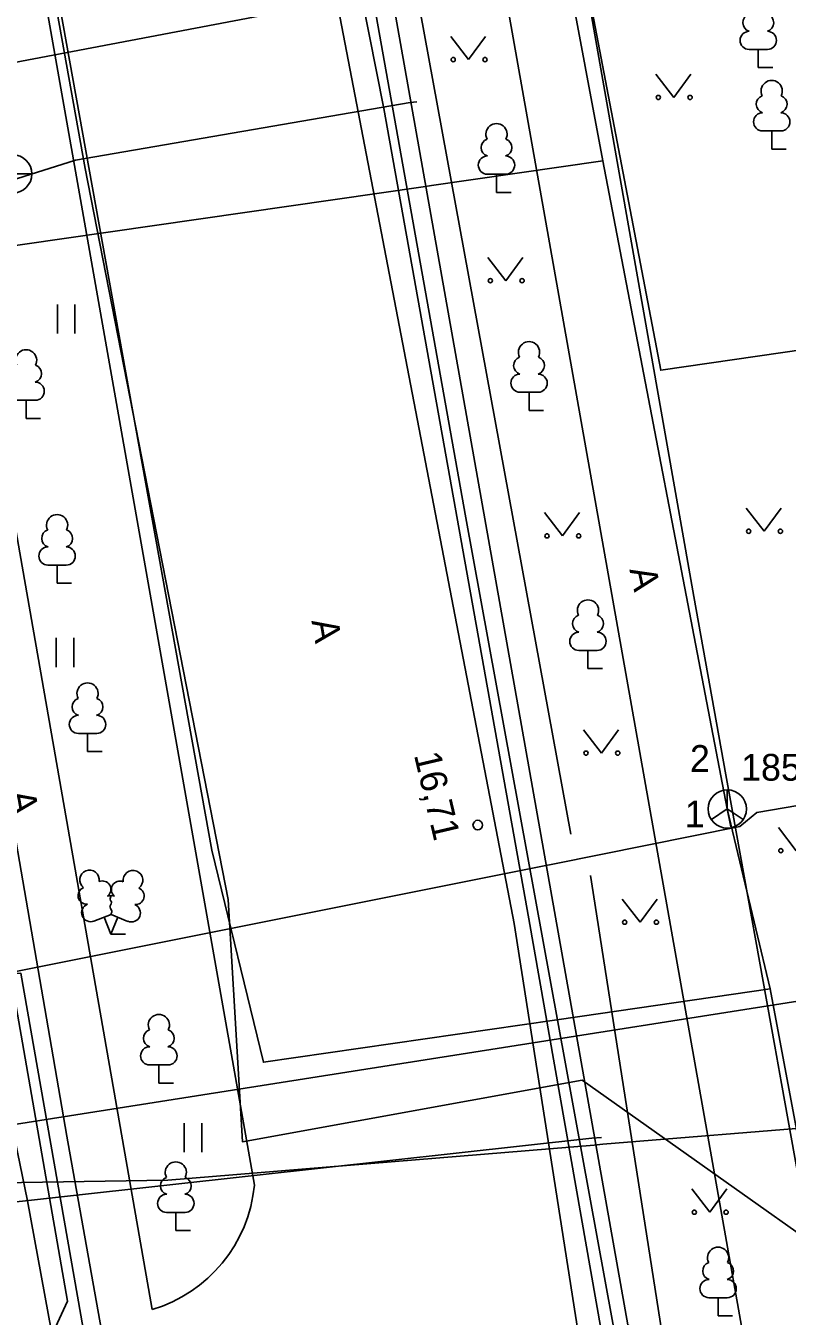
# Model space of a CAD drawing. Extents: x 713540 to 713867, y 6589774 to 6590061.
# Drawn here: x 713700.77 to 713720.66, y 6589807.61 to 6589841.34 of the extents above; entities that cross this region are included whole.
import ezdxf

# ---------------------------------------------------------------- set-up
doc = ezdxf.new("R2010")
doc.units = 0
for name, color, linetype in [('HALJASTUS', 7, 'Continuous'), ('HOONE', 7, 'Continuous'), ('KAEVU_NR', 7, 'Continuous'), ('KKAEV', 7, 'Continuous'), ('KORGUS', 7, 'Continuous'), ('KPKAABEL', 7, 'Continuous'), ('KTRASS', 7, 'Continuous'), ('MPKAABEL', 7, 'Continuous'), ('PUU', 7, 'Continuous'), ('SIKAEV', 7, 'Continuous'), ('SITRASS', 7, 'Continuous'), ('TEE', 7, 'Continuous'), ('TORU NR', 7, 'Continuous'), ('TTRASS', 7, 'Continuous'), ('VTRASS', 7, 'Continuous'), ('Слой 1', 7, 'Continuous')]:
    doc.layers.add(name, color=color, linetype=linetype)

msp = doc.modelspace()

# ---------------------------------------------------------------- linework, layer by layer
at = {"layer": 'HALJASTUS'}
for p, q in [((713711.877, 6589841.067), (713712.34, 6589840.46)), ((713712.34, 6589840.46), (713712.786, 6589841.067)), ((713717.237, 6589840.077), (713717.7, 6589839.47)), ((713717.7, 6589839.47), (713718.146, 6589840.077)), ((713712.847, 6589835.287), (713713.31, 6589834.68)), ((713713.31, 6589834.68), (713713.756, 6589835.287)), ((713701.6, 6589834.059), (713701.6, 6589833.298)), ((713702.055, 6589834.059), (713702.055, 6589833.298)), ((713714.327, 6589828.617), (713714.79, 6589828.01)), ((713714.79, 6589828.01), (713715.236, 6589828.617)), ((713719.597, 6589828.737), (713720.06, 6589828.13)), ((713720.06, 6589828.13), (713720.506, 6589828.737)), ((713701.567, 6589825.341), (713701.567, 6589824.58)), ((713702.023, 6589825.341), (713702.023, 6589824.58)), ((713715.347, 6589822.937), (713715.81, 6589822.33)), ((713715.81, 6589822.33), (713716.256, 6589822.937)), ((713720.437, 6589820.387), (713720.9, 6589819.78)), ((713716.357, 6589818.517), (713716.82, 6589817.91)), ((713716.82, 6589817.91), (713717.266, 6589818.517)), ((713704.912, 6589812.657), (713704.912, 6589811.896)), ((713705.367, 6589812.657), (713705.367, 6589811.896)), ((713718.177, 6589810.937), (713718.64, 6589810.33)), ((713718.64, 6589810.33), (713719.086, 6589810.937))]:
    msp.add_line(p, q, dxfattribs=at)
for points in [[(713705.159, 6589874.056), (713715.01, 6589820.21)], [(713718.296, 6589801.399), (713715.53, 6589819.13)]]:
    msp.add_lwpolyline(points, dxfattribs=at)
for centre in [(713711.939, 6589840.46), (713712.768, 6589840.46), (713717.299, 6589839.47), (713718.128, 6589839.47), (713712.909, 6589834.68), (713713.738, 6589834.68), (713719.659, 6589828.13), (713720.488, 6589828.13), (713714.389, 6589828.01), (713715.218, 6589828.01), (713715.409, 6589822.33), (713716.238, 6589822.33), (713720.499, 6589819.78), (713716.419, 6589817.91), (713717.248, 6589817.91), (713718.239, 6589810.33), (713719.068, 6589810.33)]:
    msp.add_circle(centre, 0.055, dxfattribs=at)
at = {"layer": 'HOONE'}
for points in [[(713671.44, 6589834.87), (713687.15, 6589837.855), (713710.253, 6589842.245), (713710.463, 6589842.286), (713715.96, 6589843.33), (713717, 6589843.42)], [(713691.059, 6589811.144), (713725.368, 6589816.545)]]:
    msp.add_lwpolyline(points, dxfattribs=at)
at = {"layer": 'KKAEV'}
msp.add_line((713699.931, 6589837.471), (713700.931, 6589837.471), dxfattribs=at)
msp.add_circle((713700.431, 6589837.471), 0.5, dxfattribs=at)
at = {"layer": 'KORGUS'}
msp.add_circle((713712.58, 6589820.45), 0.125, dxfattribs=at)
at = {"layer": 'KPKAABEL'}
for points in [[(713700.447, 6589886.145), (713701.061, 6589885.962), (713701.248, 6589885.623), (713703.334, 6589872.63), (713704.833, 6589863.294), (713707.784, 6589847.812), (713713.528, 6589817.88), (713715.336, 6589806.351), (713717.846, 6589793.663), (713718.024, 6589793.474), (713722.293, 6589793.794), (713723.951, 6589793.699), (713735.68, 6589793.289), (713735.884, 6589793.19), (713735.895, 6589792.126)], [(713736.4, 6589792.129), (713736.273, 6589793.498), (713736.211, 6589793.555), (713728.781, 6589794.331), (713726.012, 6589794.505), (713722.026, 6589794.438), (713718.442, 6589794.01), (713718.345, 6589794.091), (713715.955, 6589806.397), (713713.917, 6589817.996), (713710.127, 6589839.185), (713708.399, 6589847.895)]]:
    msp.add_lwpolyline(points, dxfattribs=at)
at = {"layer": 'KTRASS'}
msp.add_lwpolyline([(713719.19, 6589820.4), (713719.1, 6589820.87)], dxfattribs=at)
at = {"layer": 'MPKAABEL'}
for points in [[(713694.011, 6589938.961), (713692.89, 6589933.64), (713698.13, 6589925.84), (713701.56, 6589922.83), (713707.37, 6589919), (713707.983, 6589913.318), (713708.27, 6589910.66), (713700.37, 6589905.55), (713699.23, 6589901.46), (713701.24, 6589889.8), (713704.212, 6589873.404), (713706.92, 6589858.46), (713712.25, 6589828.58), (713717.93, 6589797.45), (713721.28, 6589780.69), (713722.515, 6589774.068)], [(713733.391, 6589792.128), (713732.429, 6589795.958), (713729.329, 6589801.34), (713725.485, 6589806.569), (713715.308, 6589813.781), (713706.433, 6589812.173), (713706.056, 6589818.501), (713702.321, 6589837.617), (713696.514, 6589869.947), (713694.084, 6589874.558), (713687.448, 6589873.302), (713670.227, 6589869.773), (713666.658, 6589869.039)], [(713710.985, 6589839.36), (713710.816, 6589839.338), (713702.066, 6589837.833), (713696.99, 6589836.226), (713687.666, 6589835.577)], [(713633.563, 6589809.916), (713654.618, 6589810.191), (713654.93, 6589810.196), (713666.083, 6589810.341), (713690.526, 6589810.39), (713694.651, 6589811.012), (713704.48, 6589811.17), (713715.623, 6589812.086), (713715.845, 6589812.105), (713721.87, 6589812.6), (713723.29, 6589804.72), (713724.128, 6589800.265), (713724.224, 6589799.756), (713726.25, 6589788.99), (713732.01, 6589789.32)], [(713715.814, 6589812.279), (713715.56, 6589812.268), (713706.735, 6589811.288), (713694.54, 6589809.938), (713689.415, 6589809.721), (713680.928, 6589809.941), (713675.266, 6589809.808), (713670.351, 6589809.668), (713669.919, 6589807.051), (713670.914, 6589801.264), (713671.131, 6589797.032)]]:
    msp.add_lwpolyline(points, dxfattribs=at)
at = {"layer": 'PUU'}
for p, q in [((713720.15, 6589840.725), (713719.67, 6589840.725)), ((713719.91, 6589840.25), (713719.91, 6589840.725)), ((713720.29, 6589840.25), (713719.91, 6589840.25)), ((713720.5, 6589838.595), (713720.02, 6589838.595)), ((713720.26, 6589838.12), (713720.26, 6589838.595)), ((713720.64, 6589838.12), (713720.26, 6589838.12)), ((713713.31, 6589837.465), (713712.83, 6589837.465)), ((713713.07, 6589836.99), (713713.07, 6589837.465)), ((713713.45, 6589836.99), (713713.07, 6589836.99)), ((713701.02, 6589831.555), (713700.54, 6589831.555)), ((713700.78, 6589831.08), (713700.78, 6589831.555)), ((713714.16, 6589831.765), (713713.68, 6589831.765)), ((713713.92, 6589831.29), (713713.92, 6589831.765)), ((713714.3, 6589831.29), (713713.92, 6589831.29)), ((713701.16, 6589831.08), (713700.78, 6589831.08)), ((713701.83, 6589827.245), (713701.35, 6589827.245)), ((713701.59, 6589826.77), (713701.59, 6589827.245)), ((713701.97, 6589826.77), (713701.59, 6589826.77)), ((713715.7, 6589825.015), (713715.22, 6589825.015)), ((713715.46, 6589824.54), (713715.46, 6589825.015)), ((713715.84, 6589824.54), (713715.46, 6589824.54)), ((713702.625, 6589822.844), (713702.145, 6589822.844)), ((713702.385, 6589822.369), (713702.385, 6589822.844)), ((713702.765, 6589822.369), (713702.385, 6589822.369)), ((713702.553, 6589817.937), (713702.998, 6589818.112)), ((713702.993, 6589817.602), (713702.818, 6589818.042)), ((713702.993, 6589817.602), (713703.173, 6589818.042)), ((713702.998, 6589818.112), (713703.438, 6589817.932)), ((713703.373, 6589817.602), (713702.993, 6589817.602)), ((713704.488, 6589814.178), (713704.008, 6589814.178)), ((713704.248, 6589813.703), (713704.248, 6589814.178)), ((713704.628, 6589813.703), (713704.248, 6589813.703)), ((713704.931, 6589810.323), (713704.451, 6589810.323)), ((713704.691, 6589809.848), (713704.691, 6589810.323)), ((713705.071, 6589809.848), (713704.691, 6589809.848)), ((713719.1, 6589808.095), (713718.62, 6589808.095)), ((713718.86, 6589807.62), (713718.86, 6589808.095)), ((713719.24, 6589807.62), (713718.86, 6589807.62))]:
    msp.add_line(p, q, dxfattribs=at)
msp.add_lwpolyline([(713702.998, 6589818.607), (713702.978, 6589818.532), (713702.978, 6589818.512), (713702.988, 6589818.482), (713703.008, 6589818.447), (713703.013, 6589818.427), (713702.998, 6589818.392), (713702.973, 6589818.342), (713702.968, 6589818.317), (713702.973, 6589818.302), (713702.983, 6589818.272), (713703.018, 6589818.212), (713703.023, 6589818.192), (713703.018, 6589818.172), (713703.003, 6589818.137), (713702.998, 6589818.112)], dxfattribs=at)
for centre, radius, start, end in [((713719.74, 6589841.423), 0.233, 109.0217, 253.1415), ((713720.08, 6589841.423), 0.233, 286.8508, 70.9859), ((713719.673, 6589840.962), 0.238, 90.0016, 269.3953), ((713720.147, 6589840.962), 0.238, 270.6047, 89.9984), ((713720.26, 6589839.64), 0.277, 332.5799, 207.4201), ((713720.09, 6589839.293), 0.233, 109.0217, 253.1415), ((713720.43, 6589839.293), 0.233, 286.8508, 70.9859), ((713720.023, 6589838.832), 0.238, 90.0016, 269.3953), ((713720.497, 6589838.832), 0.238, 270.6047, 89.9984), ((713713.07, 6589838.51), 0.277, 332.5799, 207.4201), ((713712.9, 6589838.163), 0.233, 109.0217, 253.1415), ((713713.24, 6589838.163), 0.233, 286.8508, 70.9859), ((713712.833, 6589837.702), 0.238, 90.0016, 269.3953), ((713713.307, 6589837.702), 0.238, 270.6047, 89.9984), ((713700.78, 6589832.6), 0.277, 332.5799, 207.4201), ((713713.92, 6589832.81), 0.277, 332.5799, 207.4201), ((713700.95, 6589832.253), 0.233, 286.8508, 70.9859), ((713713.75, 6589832.463), 0.233, 109.0217, 253.1415), ((713714.09, 6589832.463), 0.233, 286.8508, 70.9859), ((713713.683, 6589832.002), 0.238, 90.0016, 269.3953), ((713714.157, 6589832.002), 0.238, 270.6047, 89.9984), ((713701.017, 6589831.792), 0.238, 270.6047, 89.9984), ((713701.59, 6589828.29), 0.277, 332.5799, 207.4201), ((713701.42, 6589827.943), 0.233, 109.0217, 253.1415), ((713701.76, 6589827.943), 0.233, 286.8508, 70.9859), ((713701.353, 6589827.482), 0.238, 90.0016, 269.3953), ((713701.827, 6589827.482), 0.238, 270.6047, 89.9984), ((713715.46, 6589826.06), 0.277, 332.5799, 207.4201), ((713715.29, 6589825.713), 0.233, 109.0217, 253.1415), ((713715.63, 6589825.713), 0.233, 286.8508, 70.9859), ((713715.223, 6589825.252), 0.238, 90.0016, 269.3953), ((713715.697, 6589825.252), 0.238, 270.6047, 89.9984), ((713702.385, 6589823.889), 0.277, 332.5799, 207.4201), ((713702.215, 6589823.541), 0.233, 109.0217, 253.1415), ((713702.555, 6589823.541), 0.233, 286.8508, 70.9859), ((713702.147, 6589823.081), 0.238, 90.0016, 269.3953), ((713702.622, 6589823.081), 0.238, 270.6047, 89.9984), ((713702.436, 6589819.017), 0.256, 111.5027, 232.5173), ((713702.436, 6589819.017), 0.256, 350.4856, 111.5002), ((713702.77, 6589818.766), 0.224, 308.5041, 111.5725), ((713703.234, 6589818.761), 0.225, 67.7016, 230.5126), ((713703.572, 6589819.008), 0.256, 67.6168, 188.6314), ((713703.572, 6589819.008), 0.256, 306.5997, 67.6143), ((713702.362, 6589818.605), 0.224, 111.4304, 274.4987), ((713703.639, 6589818.595), 0.224, 264.6183, 67.6866), ((713702.467, 6589818.161), 0.237, 111.5014, 291.5004), ((713702.997, 6589818.37), 0.237, 66.7655, 111.5015), ((713703.528, 6589818.153), 0.237, 247.6166, 67.6155), ((713704.248, 6589815.223), 0.277, 332.5799, 207.4201), ((713704.078, 6589814.876), 0.233, 109.0217, 253.1415), ((713704.418, 6589814.876), 0.233, 286.8508, 70.9859), ((713704.01, 6589814.416), 0.238, 90.0016, 269.3953), ((713704.485, 6589814.416), 0.238, 270.6047, 89.9984), ((713704.691, 6589811.368), 0.277, 332.5799, 207.4201), ((713704.521, 6589811.02), 0.233, 109.0217, 253.1415), ((713704.861, 6589811.02), 0.233, 286.8508, 70.9859), ((713704.454, 6589810.56), 0.238, 90.0016, 269.3953), ((713704.929, 6589810.56), 0.238, 270.6047, 89.9984), ((713718.86, 6589809.14), 0.277, 332.5799, 207.4201), ((713718.69, 6589808.793), 0.233, 109.0217, 253.1415), ((713719.03, 6589808.793), 0.233, 286.8508, 70.9859), ((713718.623, 6589808.332), 0.238, 90.0016, 269.3953), ((713719.097, 6589808.332), 0.238, 270.6047, 89.9984)]:
    msp.add_arc(centre, radius, start, end, dxfattribs=at)
at = {"layer": 'SIKAEV'}
for p, q in [((713719.1, 6589821.37), (713719.1, 6589820.87)), ((713719.1, 6589820.87), (713718.685, 6589820.595)), ((713719.1, 6589820.87), (713719.515, 6589820.595))]:
    msp.add_line(p, q, dxfattribs=at)
msp.add_circle((713719.1, 6589820.87), 0.5, dxfattribs=at)
at = {"layer": 'SITRASS'}
for points in [[(713622.526, 6589942.802), (713625.02, 6589914.21), (713630.01, 6589903.07), (713639.36, 6589886.76), (713642.3, 6589872.04), (713652.19, 6589865.47), (713653.052, 6589864.917), (713657.52, 6589862.05), (713661.076, 6589847.8), (713664.28, 6589834.96), (713666.33, 6589831.93), (713670.966, 6589832.394), (713671.39, 6589832.436), (713687.742, 6589834.073), (713694.81, 6589834.78), (713711.155, 6589837.134), (713711.376, 6589837.166), (713715.85, 6589837.81)], [(713708.693, 6589877.993), (713708.41, 6589877.3), (713708.797, 6589875.248), (713714.46, 6589845.22), (713715.85, 6589837.81), (713719.1, 6589820.87), (713720.22, 6589816.17)], [(713615.75, 6589870.91), (713621.3, 6589860.3), (713625.233, 6589860.869), (713625.227, 6589860.885), (713640.96, 6589863.23), (713652.708, 6589865.606), (713653.172, 6589865.67), (713666.653, 6589868.422), (713666.793, 6589868.454), (713693.51, 6589873.89), (713696.19, 6589872.18), (713705.63, 6589819.79), (713706.98, 6589814.25), (713714.585, 6589815.353), (713715.248, 6589815.449), (713720.22, 6589816.17), (713721.73, 6589808.13), (713722.95, 6589800.79), (713723.002, 6589800.484), (713723.148, 6589799.687), (713725.92, 6589783.295)], [(713692.355, 6589841.896), (713696.3, 6589835.59), (713698.99, 6589819.49), (713700.82, 6589810.63), (713702.44, 6589801.79), (713704.26, 6589791.98), (713706.2, 6589780.63), (713707.441, 6589774.068)]]:
    msp.add_lwpolyline(points, dxfattribs=at)
at = {"layer": 'TEE'}
for points in [[(713709.501, 6589875.479), (713713.392, 6589853.877), (713718.226, 6589826.424), (713719.066, 6589821.759), (713719.238, 6589820.801), (713720.341, 6589814.674), (713720.518, 6589813.69), (713723.269, 6589798.406), (713724.259, 6589792.837)], [(713704.07, 6589807.784), (713692.349, 6589874.816)], [(713707.371, 6589874.781), (713711.263, 6589853.673), (713719.667, 6589806.269), (713718.326, 6589806.164), (713716.499, 6589807.387), (713708.381, 6589853.164), (713704.698, 6589873.833)], [(713706.743, 6589811.038), (713701.269, 6589842.093), (713695.587, 6589873.867)], [(713696.453, 6589839.015), (713701.863, 6589808.006), (713701.336, 6589806.867)]]:
    msp.add_lwpolyline(points, dxfattribs=at)
msp.add_arc((713703.002, 6589811.387), 3.758, 286.5169, 354.6751, dxfattribs=at)
at = {"layer": 'TTRASS'}
for points in [[(713726.71, 6589821.95), (713719.87, 6589820.78), (713719.43, 6589820.41)], [(713719.43, 6589820.41), (713714.539, 6589819.43), (713714.316, 6589819.386), (713685.752, 6589813.666)]]:
    msp.add_lwpolyline(points, dxfattribs=at)
at = {"layer": 'VTRASS'}
msp.add_lwpolyline([(713708.725, 6589774.068), (713707.065, 6589783.601), (713705.018, 6589794.55), (713701.84, 6589812.321), (713699.235, 6589827.436), (713699.875, 6589827.579), (713696.888, 6589845.261), (713694.289, 6589860.829), (713691.539, 6589877.243), (713690.275, 6589883.906), (713690.135, 6589884.996), (713689.231, 6589889.843), (713687.737, 6589897.698), (713684.897, 6589913.25), (713684.491, 6589918.952), (713684.308, 6589921.181)], dxfattribs=at)
at = {"layer": 'Слой 1'}
for points in [[(713754.51, 6589852.01), (713745.66, 6589837.3), (713737.02, 6589835.72), (713729.39, 6589834.08), (713717.36, 6589832.34), (713707.43, 6589884.34), (713724.46, 6589897.32), (713765.74, 6589876.63)], [(713706.95, 6589780.62), (713633.23, 6589779.53), (713631.93, 6589779.47), (713632.04, 6589786.08), (713631.13, 6589786.14), (713631.13, 6589806.31), (713631.28, 6589816.48), (713700.64, 6589816.58)]]:
    msp.add_lwpolyline(points, close=True, dxfattribs=at)

# ---------------------------------------------------------------- texts
at = {"layer": 'KAEVU_NR'}
msp.add_text('1856', height=0.7, dxfattribs=at).set_placement((713719.46, 6589821.61))
at = {"layer": 'KORGUS'}
msp.add_text('16,71', height=0.7, rotation=283.2774, dxfattribs=at).set_placement((713710.91, 6589822.284))
at = {"layer": 'TEE'}
for rotation, p in [(282.2826, (713716.54, 6589827.13)), (279.8872, (713708.233, 6589825.79)), (280.1296, (713700.318, 6589821.304))]:
    msp.add_text('A', height=0.7, rotation=rotation, dxfattribs=at).set_placement(p)
at = {"layer": 'TORU NR'}
for s, p in [('2', (713718.124, 6589821.84)), ('1', (713717.988, 6589820.39))]:
    msp.add_text(s, height=0.7, dxfattribs=at).set_placement(p)

doc.saveas('drawing.dxf')
